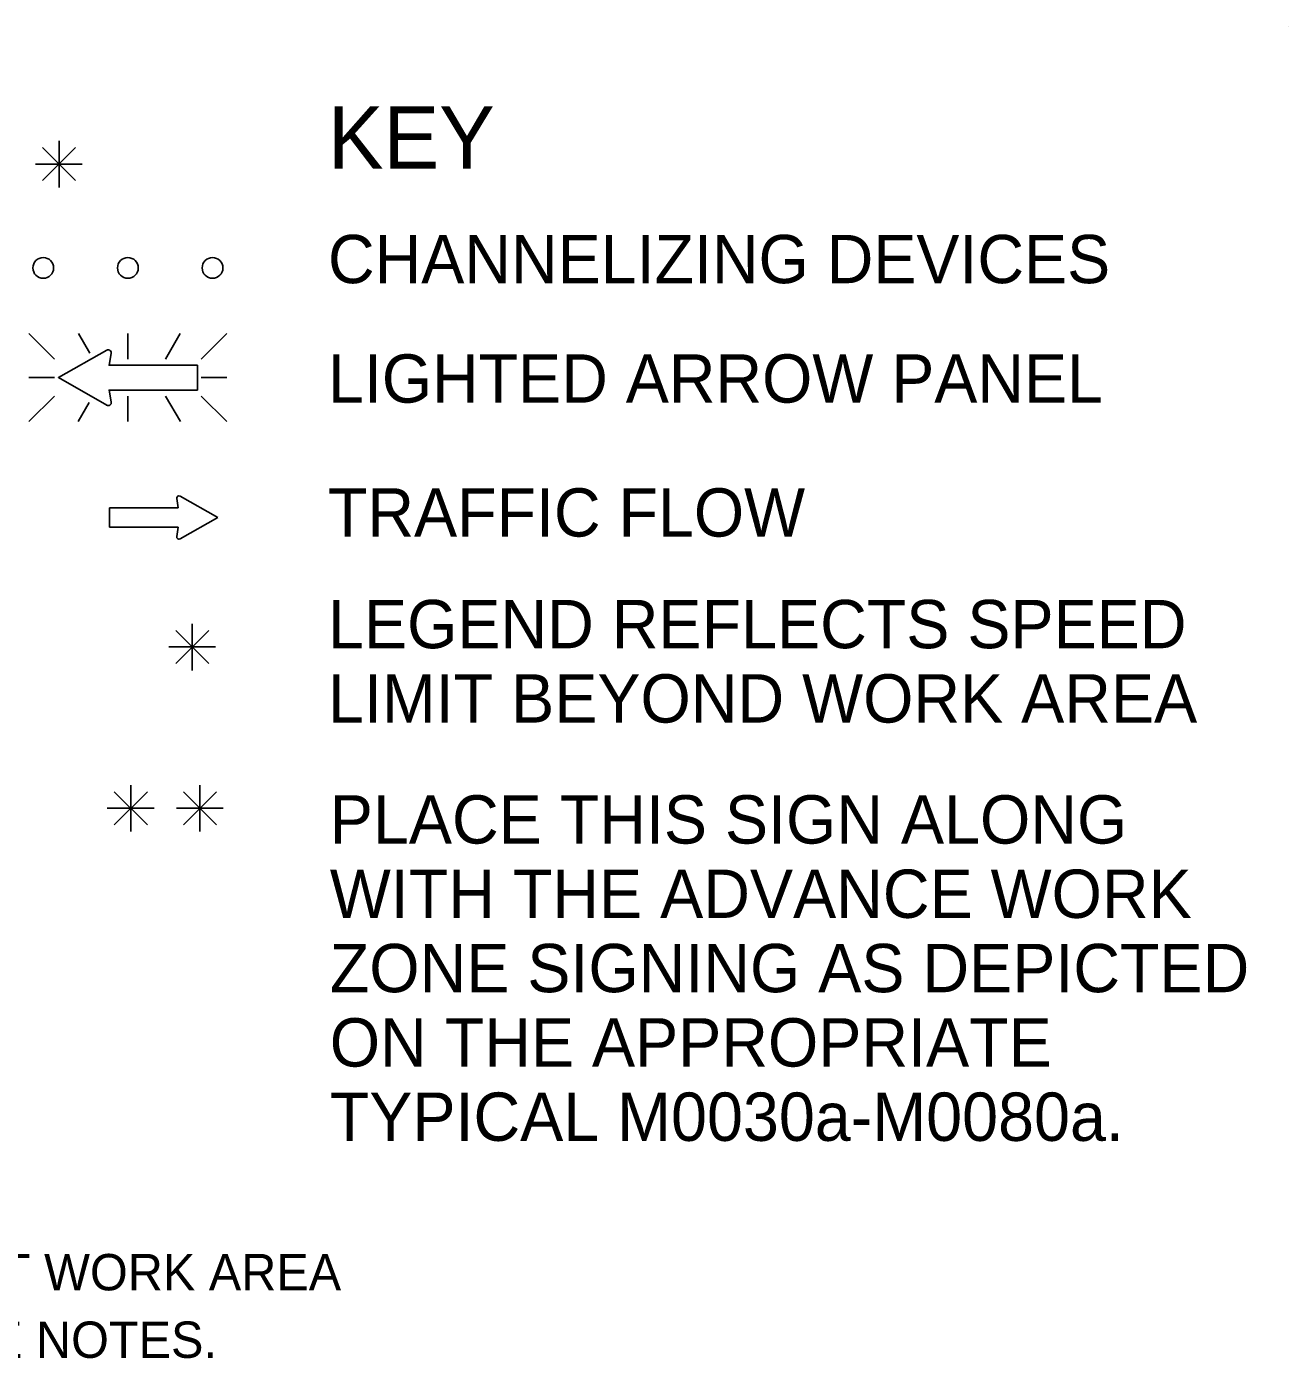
# Model space of a CAD drawing. Extents: x 16576 to 19508, y 5728 to 6974.
# Drawn here: x 18207.5 to 18450.5, y 6674.4 to 6930.8 of the extents above; entities that cross this region are included whole.
import ezdxf

# ---------------------------------------------------------------- set-up
doc = ezdxf.new("R2010")
doc.units = 0
for name, color, linetype in [('BORDER', 7, 'Continuous'), ('MT_SCRATCH_LEVEL_E', 7, 'Continuous'), ('TRAFFIC_SIGNS_PR', 7, 'Continuous'), ('TYPICAL_TEXT_DIMEN_EX', 7, 'Continuous'), ('TYPICAL_TEXT_DIMEN_PR', 7, 'Continuous')]:
    doc.layers.add(name, color=color, linetype=linetype)

msp = doc.modelspace()

# ---------------------------------------------------------------- linework, layer by layer
at = {"layer": 'BORDER'}
msp.add_line((18450.55, 6930.8), (18450.55, 6930.8), dxfattribs=at)
at = {"layer": 'MT_SCRATCH_LEVEL_E'}
for p, q in [((18236.44, 6839.92), (18236.75, 6838.14)), ((18244.36, 6836.29), (18237.12, 6840.4)), ((18236.75, 6838.14), (18223.5, 6838.14)), ((18223.5, 6838.14), (18223.5, 6834.4)), ((18237.12, 6832.15), (18244.36, 6836.29)), ((18223.5, 6834.4), (18236.75, 6834.4)), ((18236.75, 6834.4), (18236.44, 6832.62))]:
    msp.add_line(p, q, dxfattribs=at)
for centre, start, end in [((18236.9, 6839.99), 60.4248, 189.9638), ((18236.9, 6832.55), 170.0362, 299.7731)]:
    msp.add_arc(centre, 0.463, start, end, dxfattribs=at)
at = {"layer": 'TRAFFIC_SIGNS_PR'}
for p, q in [((18207.95, 6871.72), (18212.88, 6866.79)), ((18219.71, 6867.9), (18217.5, 6871.72)), ((18227.03, 6866.79), (18227.03, 6871.72)), ((18234.26, 6866.79), (18237.11, 6871.72)), ((18241.18, 6866.79), (18246.11, 6871.72)), ((18212.88, 6863.23), (18207.95, 6863.23)), ((18241.18, 6863.23), (18246.11, 6863.23)), ((18207.95, 6854.74), (18212.88, 6859.68)), ((18227.03, 6859.68), (18227.03, 6854.74)), ((18237.16, 6854.74), (18234.31, 6859.68)), ((18241.18, 6859.68), (18246.11, 6854.74)), ((18217.46, 6854.74), (18219.57, 6858.4))]:
    msp.add_line(p, q, dxfattribs=at)
for points in [[(18222.96, 6868.51), (18213.67, 6863.23), (18222.96, 6857.91)], [(18223.83, 6858.54), (18223.43, 6860.81), (18240.44, 6860.81), (18240.44, 6865.61), (18223.43, 6865.61), (18223.83, 6867.89)]]:
    msp.add_lwpolyline(points, dxfattribs=at)
for centre in [(18210.74, 6884.34), (18227.04, 6884.34), (18243.34, 6884.34)]:
    msp.add_circle(centre, 2, dxfattribs=at)
for centre, radius, start, end in [((18223.25, 6867.98), 0.598, 350.7308, 118.8916), ((18223.24, 6858.43), 0.597, 241.4833, 9.9593)]:
    msp.add_arc(centre, radius, start, end, dxfattribs=at)
at = {"layer": 'TYPICAL_TEXT_DIMEN_EX'}
for p, q in [((18239.43, 6811.36), (18239.43, 6815.82)), ((18236.25, 6814.55), (18242.62, 6808.17)), ((18242.62, 6814.55), (18236.25, 6808.17)), ((18239.43, 6811.36), (18234.9, 6811.36)), ((18239.43, 6811.36), (18242.62, 6811.36)), ((18239.43, 6811.36), (18243.91, 6811.36)), ((18239.43, 6811.36), (18239.43, 6806.86)), ((18224.42, 6783.48), (18230.8, 6777.11)), ((18230.8, 6783.48), (18224.42, 6777.11)), ((18227.61, 6780.3), (18227.61, 6784.75)), ((18237.74, 6783.48), (18244.12, 6777.11)), ((18244.12, 6783.48), (18237.74, 6777.11)), ((18240.93, 6780.3), (18240.93, 6784.75)), ((18227.61, 6780.3), (18223.08, 6780.3)), ((18227.61, 6780.3), (18230.8, 6780.3)), ((18227.61, 6780.3), (18232.08, 6780.3)), ((18227.61, 6780.3), (18227.61, 6775.8)), ((18240.93, 6780.3), (18236.4, 6780.3)), ((18240.93, 6780.3), (18244.12, 6780.3)), ((18240.93, 6780.3), (18245.41, 6780.3)), ((18240.93, 6780.3), (18240.93, 6775.8))]:
    msp.add_line(p, q, dxfattribs=at)
at = {"layer": 'TYPICAL_TEXT_DIMEN_PR'}
for p, q in [((18213.78, 6904.34), (18213.78, 6908.8)), ((18216.97, 6907.53), (18210.59, 6901.15)), ((18210.6, 6907.53), (18216.97, 6901.15)), ((18213.78, 6904.34), (18209.25, 6904.34)), ((18213.78, 6904.34), (18216.97, 6904.34)), ((18213.78, 6904.34), (18218.26, 6904.34)), ((18213.78, 6904.34), (18213.78, 6899.84))]:
    msp.add_line(p, q, dxfattribs=at)

# ---------------------------------------------------------------- texts
at = {"layer": 'TRAFFIC_SIGNS_PR'}
for s, p in [('PLACE THROUGHOUT WORK AREA', (18107.93, 6687.48)), ('AS INDICATED IN THE NOTES.', (18107.93, 6674.48))]:
    msp.add_text(s, height=7, dxfattribs=at).set_placement(p)
at = {"layer": 'TYPICAL_TEXT_DIMEN_EX'}
for s, height, p in [('KEY', 12, (18265.58, 6903.45)), ('CHANNELIZING DEVICES', 9.3, (18265.58, 6881.4)), ('LIGHTED ARROW PANEL', 9.3, (18265.58, 6858.4)), ('TRAFFIC FLOW', 9.3, (18265.58, 6832.61)), ('LEGEND REFLECTS SPEED', 9.31, (18265.58, 6811.11)), ('LIMIT BEYOND WORK AREA', 9.31, (18265.58, 6796.8)), ('PLACE THIS SIGN ALONG', 9.31, (18265.93, 6773.5)), ('WITH THE ADVANCE WORK', 9.31, (18265.93, 6759.19)), ('ZONE SIGNING AS DEPICTED', 9.31, (18265.93, 6744.88)), ('ON THE APPROPRIATE', 9.31, (18265.93, 6730.57)), ('TYPICAL M0030a-M0080a.', 9.31, (18265.93, 6716.26))]:
    msp.add_text(s, height=height, dxfattribs=at).set_placement(p)

doc.saveas('drawing.dxf')
